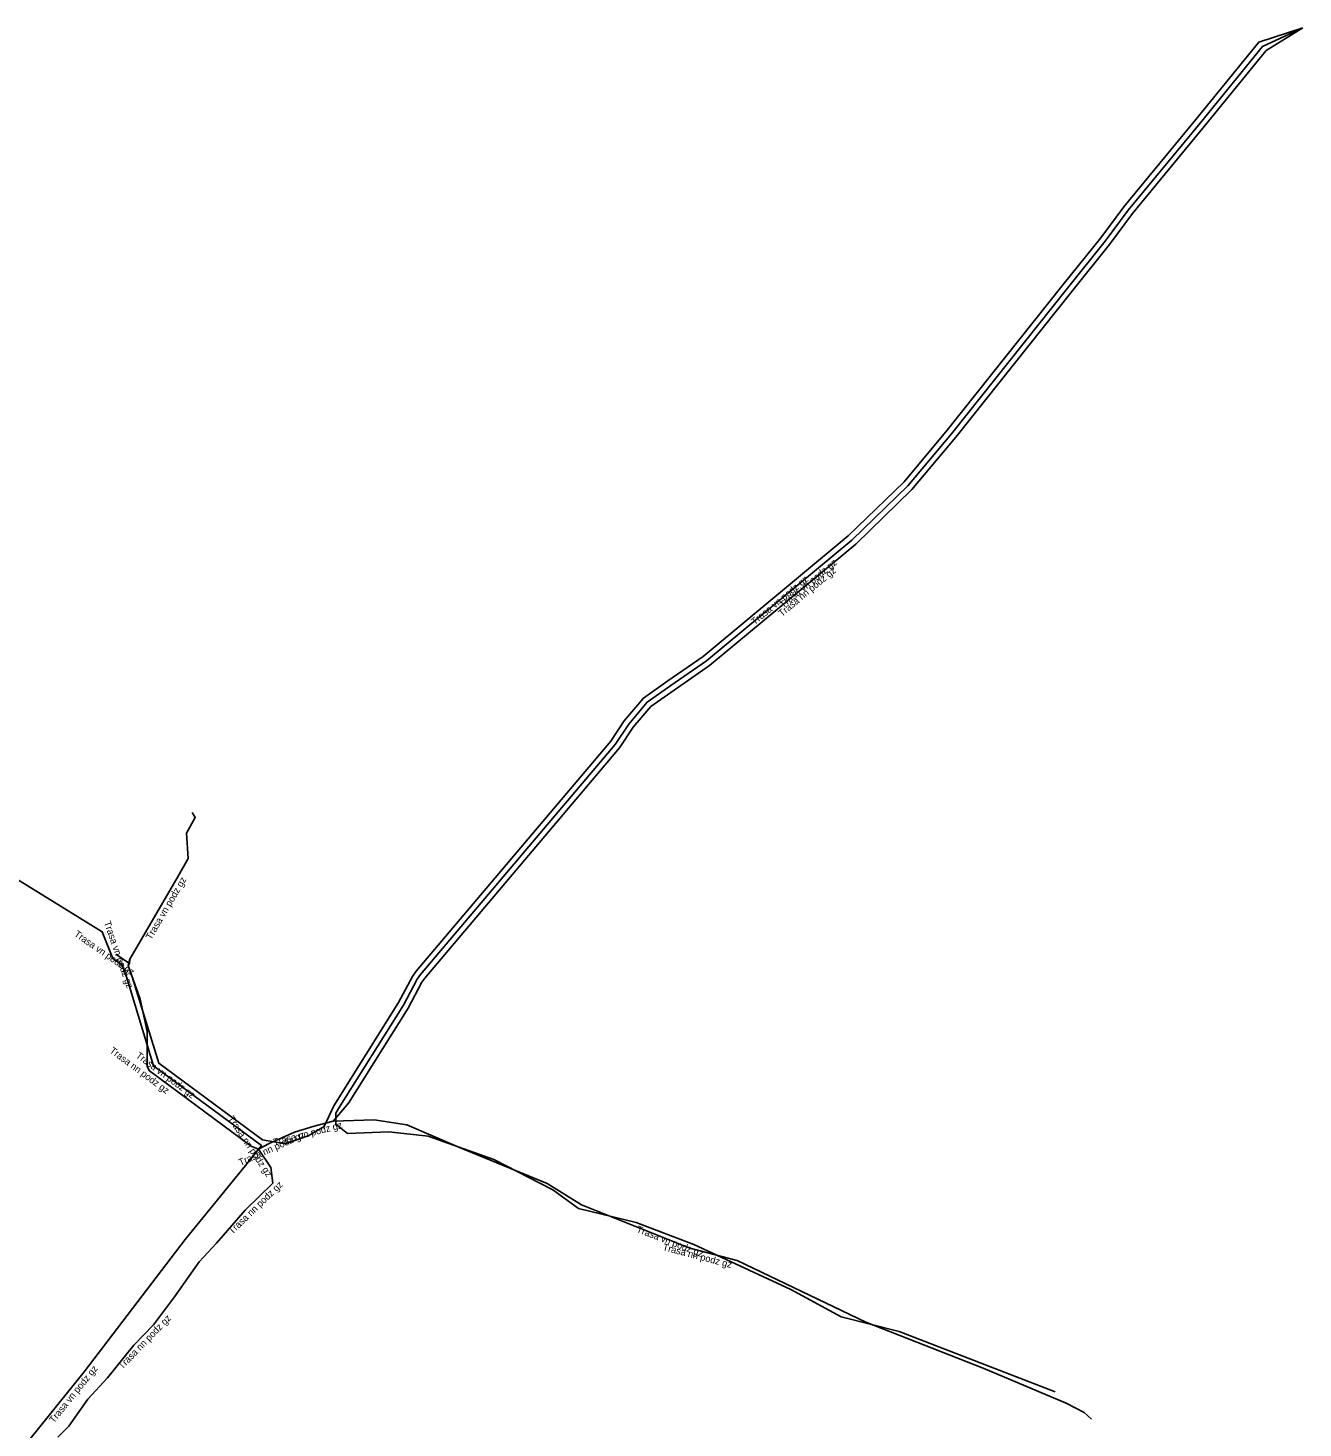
# Model space of a CAD drawing. Extents: x -686919 to -686577, y -972514 to -971911.
# Drawn here: x -686669.7 to -686577.1, y -972126.9 to -972025.2 of the extents above; entities that cross this region are included whole.
import ezdxf

# ---------------------------------------------------------------- set-up
doc = ezdxf.new("R2010")
doc.units = 0
for name, color, linetype in [('Popiskový text - Ostatní atributy Trasy', 7, 'Continuous'), ('Spojnice NN', 7, 'Continuous'), ('Spojnice VN', 7, 'Continuous')]:
    doc.layers.add(name, color=color, linetype=linetype)

msp = doc.modelspace()

# ---------------------------------------------------------------- linework, layer by layer
at = {"layer": 'Spojnice NN'}
for points in [[(-686577.11, -972025.2), (-686579.79, -972026.84), (-686584.28, -972032.36), (-686589.5, -972038.69), (-686591.17, -972040.93), (-686593.91, -972044.35), (-686602.34, -972054.93), (-686605.52, -972058.73), (-686609.61, -972062.71), (-686620.22, -972071.52), (-686622.81, -972073.31), (-686624.49, -972074.5), (-686625.78, -972076.02), (-686626.77, -972077.51), (-686640.92, -972094.24), (-686641.14, -972094.54), (-686642.12, -972096.42), (-686646.47, -972103.34), (-686647.57, -972104.64)], [(-686652.99, -972106.67), (-686653.54, -972106.46), (-686660.91, -972100.99), (-686661.08, -972100.66), (-686661.08, -972098.12), (-686661.59, -972095.77), (-686662.46, -972093.33), (-686662.36, -972092.88)], [(-686648.96, -972105), (-686650.38, -972105.45), (-686652.23, -972106.27), (-686652.99, -972106.67)], [(-686648.96, -972105), (-686647.57, -972104.64)], [(-686592.47, -972126.3), (-686593.02, -972125.82), (-686594.32, -972125.13), (-686600.35, -972122.6), (-686608.88, -972119.25), (-686618.22, -972114.77), (-686621.65, -972113.87), (-686629.54, -972110.72), (-686632.02, -972109.17), (-686638.39, -972106.55), (-686642.22, -972104.9), (-686644.6, -972104.55), (-686647.57, -972104.64)], [(-686652.1, -972108), (-686652.99, -972106.67)], [(-686652.1, -972108), (-686651.96, -972109.14), (-686653.98, -972111.1)], [(-686653.98, -972111.1), (-686656.05, -972113.5), (-686657.31, -972114.86), (-686659.1, -972117.4), (-686660.64, -972119.44), (-686662.07, -972120.92), (-686663.96, -972123.29), (-686665.4, -972124.84), (-686666.79, -972126.8), (-686667.59, -972127.61)]]:
    msp.add_lwpolyline(points, dxfattribs=at)
at = {"layer": 'Spojnice VN'}
for points in [[(-686577.11, -972025.2), (-686580.32, -972026.23), (-686584.9, -972031.86), (-686590.12, -972038.19), (-686591.81, -972040.44), (-686594.53, -972043.85), (-686602.96, -972054.43), (-686606.1, -972058.19), (-686610.15, -972062.11), (-686620.7, -972070.88), (-686623.27, -972072.65), (-686625.03, -972073.9), (-686626.42, -972075.54), (-686627.41, -972077.03), (-686641.54, -972093.74), (-686641.82, -972094.12), (-686642.82, -972096.02), (-686647.53, -972103.52), (-686648.23, -972105.02), (-686649.4, -972105.71), (-686651.06, -972106.28)], [(-686577.11, -972025.2), (-686580.06, -972026.54), (-686584.59, -972032.11), (-686589.81, -972038.44), (-686591.49, -972040.68), (-686594.22, -972044.1), (-686602.65, -972054.68), (-686605.81, -972058.46), (-686609.88, -972062.41), (-686620.46, -972071.2), (-686623.04, -972072.98), (-686624.76, -972074.2), (-686626.1, -972075.78), (-686627.09, -972077.27), (-686641.23, -972093.99), (-686641.48, -972094.33), (-686642.47, -972096.22), (-686647.19, -972103.73)], [(-686729.86, -972057.62), (-686720.3, -972057.87), (-686714.91, -972060.11), (-686708.63, -972063.82), (-686705.94, -972065.5), (-686695.21, -972072), (-686693.25, -972073.13), (-686691.55, -972074.81), (-686673.63, -972085.17), (-686664.35, -972090.87), (-686663.59, -972092.83), (-686662.9, -972093.3), (-686662.55, -972094.29), (-686660.64, -972100.63), (-686652.79, -972106.42), (-686653.94, -972107.86)], [(-686662.38, -972093.18), (-686662.36, -972092.88), (-686658.83, -972086.83), (-686658.11, -972085.55), (-686658.24, -972083.7), (-686657.6, -972082.58), (-686657.82, -972082.21)], [(-686663.36, -972092.5), (-686662.38, -972093.18)], [(-686662.17, -972094.16), (-686662.46, -972093.33), (-686662.38, -972093.18)], [(-686651.06, -972106.28), (-686652.7, -972106), (-686660.24, -972100.43), (-686662.17, -972094.16)], [(-686647.19, -972103.73), (-686647.39, -972104.05), (-686647.39, -972104.86), (-686646.53, -972105.53), (-686643.52, -972105.41), (-686640.67, -972105.73), (-686635.89, -972107.43), (-686631.61, -972109.63), (-686629.74, -972110.98), (-686625.55, -972112), (-686621.36, -972113.61), (-686614.32, -972116.87), (-686610.67, -972118.86), (-686606.46, -972119.93), (-686595.12, -972124.31)], [(-686678.56, -972137.96), (-686673.53, -972132.59), (-686665.66, -972122.86), (-686658.33, -972113.25), (-686653.94, -972107.86)]]:
    msp.add_lwpolyline(points, dxfattribs=at)

# ---------------------------------------------------------------- texts
at = {"layer": 'Popiskový text - Ostatní atributy Trasy'}
for s, rotation, p in [('Trasa nn podz gz', 39.721, (-686614.97, -972068.01)), ('Trasa vn podz gz', 39.7202, (-686614.87, -972067.4)), ('Trasa vn podz gz', 39.7195, (-686616.95, -972068.61)), ('Trasa vn podz gz', 59.7377, (-686660.8, -972091.5)), ('Trasa vn podz gz', 325.2441, (-686666.44, -972091.15)), ('Trasa vn podz gz', 289.2593, (-686664.24, -972090.2)), ('Trasa nn podz gz', 323.4173, (-686663.86, -972099.61)), ('Trasa vn podz gz', 323.5722, (-686661.96, -972099.97)), ('Trasa nn podz gz', 303.7894, (-686655.25, -972104.46)), ('Trasa nn podz gz', 14.5201, (-686651.87, -972106.43)), ('Trasa nn podz gz', 23.905, (-686654.31, -972107.9)), ('Trasa nn podz gz', 44.1363, (-686654.9, -972112.9)), ('Trasa vn podz gz', 338.9542, (-686625.58, -972112.69)), ('Trasa nn podz gz', 345.2976, (-686623.67, -972114.01)), ('Trasa nn podz gz', 45.9844, (-686662.9, -972122.71)), ('Trasa vn podz gz', 51.0327, (-686667.87, -972126.62))]:
    msp.add_text(s, height=0.5, rotation=rotation, dxfattribs=at).set_placement(p)

doc.saveas('drawing.dxf')
